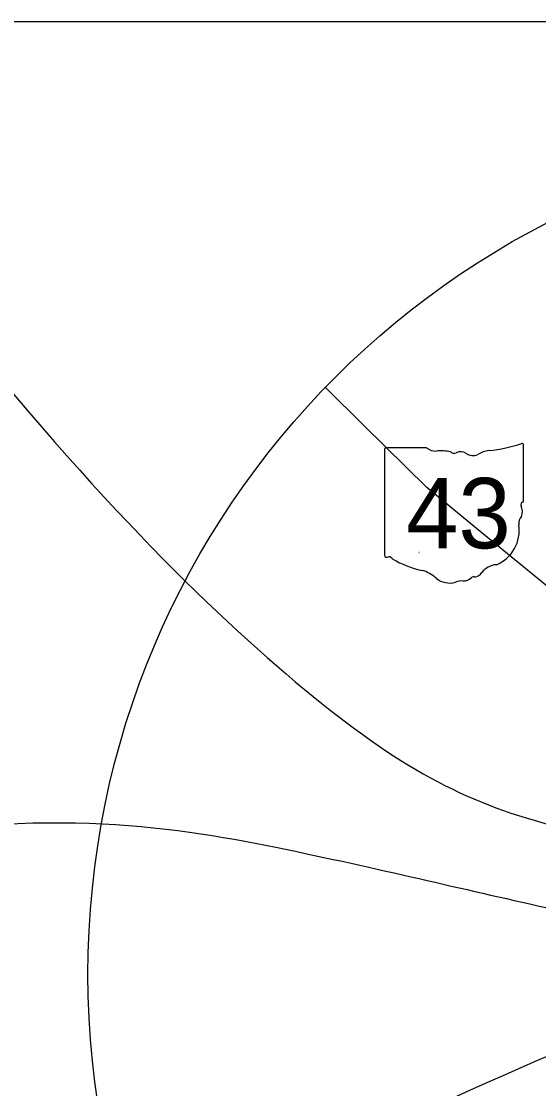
# Model space of a CAD drawing. Extents: x -202 to 1556, y 0 to 676.
# Drawn here: x 95.6 to 150.7, y 106.3 to 220 of the extents above; entities that cross this region are included whole.
import ezdxf

# ---------------------------------------------------------------- set-up
doc = ezdxf.new("R2010")
doc.units = 0
for name, color, linetype in [('Default', 7, 'Continuous'), ('GM_X_City_Street', 7, 'Continuous'), ('GM_X_Major_River_Text', 7, 'Continuous'), ('GM_X_Minor_River_Text', 7, 'Continuous'), ('SH_Data', 7, 'Continuous')]:
    doc.layers.add(name, color=color, linetype=linetype)

msp = doc.modelspace()

# ---------------------------------------------------------------- linework, layer by layer
at = {"layer": 'Default'}
msp.add_lwpolyline([(187.32, 118.77), (186.06, 119.26), (184.38, 120.64), (182.61, 122.34), (181.15, 124.21), (179.3, 126.09), (177.33, 128.46), (176.33, 129.83), (175.47, 131.38), (174.48, 133.74), (173.13, 138.32), (172.07, 141.13), (171.14, 142.74), (169.81, 144.47), (163.58, 149.95), (162.3, 151.06), (144.08, 165.95), (138.78, 170.32), (132.09, 176.89), (127.97, 181)], dxfattribs=at)
at = {"layer": 'GM_X_City_Street'}
for p, q in [((134.26, 174.37), (134.26, 163.12)), ((138.75, 174.57), (134.4, 174.57)), ((149.09, 168.96), (149.09, 174.85)), ((149.09, 168.96), (149.09, 168.96))]:
    msp.add_line(p, q, dxfattribs=at)
for centre, radius, start, end in [((134.43, 174.4), 0.172, 98.1301, 188.1301), ((139.78, 175.87), 1.67, 231.6195, 271.1119), ((140.33, 168.25), 5.98, 80.4867, 94.9883), ((141.69, 174.45), 0.481, 219.7921, 297.1024), ((142.4, 173.15), 1, 54.4667, 119.1411), ((145.81, 171.13), 3.16, 97.3462, 120.7689), ((143.81, 189.91), 15.73, 275.8445, 288.9065), ((148.92, 174.87), 0.165, 351.8621, 97.738), ((143.69, 174.94), 1.2, 233.8562, 294.8282), ((149.05, 168.52), 0.256, 107.944, 210.337), ((147.42, 167.78), 1.53, 340.033, 23.6496), ((148.91, 168.93), 0.177, 289.6038, 7.7341), ((149.68, 166.49), 1.12, 136.8065, 186.9296), ((144.69, 165.74), 3.93, 292.3089, 8.9858), ((134.43, 163.09), 0.173, 171.9584, 258.3066), ((134.46, 164.24), 1.32, 267.339, 280.6039), ((134.73, 162.47), 0.477, 29.7484, 93.2717), ((140.75, 172.58), 11.36, 240.4129, 257.1985), ((137.36, 158.06), 3.55, 47.1842, 75.836), ((146.35, 159.96), 2.15, 94.4031, 142.5768), ((141.21, 162.41), 2.26, 230.7004, 286.2918), ((142.51, 158.52), 1.85, 85.6951, 111.2099), ((142.67, 161.57), 1.2, 268.777, 315.5493), ((143.76, 160.48), 0.338, 65.7517, 132.6484), ((143.62, 162.02), 1.27, 282.8732, 323.2771)]:
    msp.add_arc(centre, radius, start, end, dxfattribs=at)
at = {"layer": 'GM_X_Major_River_Text'}
for p, q in [((143.31, 164.95), (143.31, 164.94)), ((143.31, 164.94), (143.31, 164.95)), ((143.31, 164.95), (143.31, 164.95)), ((143.32, 164.95), (143.32, 164.95)), ((143.32, 164.94), (143.32, 164.94)), ((137.95, 163.41), (137.94, 163.39)), ((137.97, 163.4), (137.96, 163.4)), ((137.96, 163.4), (137.97, 163.4)), ((137.96, 163.39), (137.96, 163.39)), ((137.97, 163.4), (137.97, 163.4)), ((137.97, 163.39), (137.97, 163.39))]:
    msp.add_line(p, q, dxfattribs=at)
msp.add_lwpolyline([(137.95, 163.41), (137.95, 163.39), (137.94, 163.39), (137.95, 163.41)], close=True, dxfattribs=at)
for points in [[(137.94, 163.39), (137.95, 163.39), (137.95, 163.39)], [(137.96, 163.39), (137.95, 163.39), (137.95, 163.41)], [(137.95, 163.39), (137.95, 163.39), (137.96, 163.39)]]:
    msp.add_lwpolyline(points, dxfattribs=at)
for points in [[(143.31, 164.94), (143.31, 164.94), (143.31, 164.95)], [(143.31, 164.95), (143.31, 164.95), (143.31, 164.95)], [(143.31, 164.95), (143.31, 164.95), (143.31, 164.95)], [(143.31, 164.95), (143.31, 164.95), (143.31, 164.95)], [(143.31, 164.95), (143.31, 164.95), (143.31, 164.95)], [(143.31, 164.95), (143.31, 164.95), (143.31, 164.95)], [(143.31, 164.95), (143.31, 164.95), (143.31, 164.95)], [(143.31, 164.95), (143.31, 164.95), (143.32, 164.95)], [(143.32, 164.95), (143.32, 164.95), (143.31, 164.95)], [(143.31, 164.95), (143.31, 164.95), (143.31, 164.95)], [(143.31, 164.95), (143.31, 164.95), (143.31, 164.95)], [(143.31, 164.95), (143.31, 164.95), (143.31, 164.95)], [(143.31, 164.95), (143.31, 164.95), (143.31, 164.95)], [(143.31, 164.95), (143.31, 164.95), (143.31, 164.95)], [(143.31, 164.95), (143.31, 164.95), (143.31, 164.95)], [(143.31, 164.95), (143.31, 164.95), (143.31, 164.95)], [(143.31, 164.95), (143.31, 164.95), (143.32, 164.94)], [(143.32, 164.95), (143.32, 164.95), (143.31, 164.95)], [(143.31, 164.95), (143.31, 164.95), (143.31, 164.95)], [(143.31, 164.95), (143.31, 164.95), (143.31, 164.95)], [(143.31, 164.95), (143.31, 164.95), (143.31, 164.95)], [(143.31, 164.95), (143.31, 164.95), (143.31, 164.95)], [(143.31, 164.95), (143.31, 164.95), (143.31, 164.95)], [(143.31, 164.95), (143.31, 164.95), (143.31, 164.95)], [(143.31, 164.95), (143.31, 164.95), (143.31, 164.95)], [(143.31, 164.95), (143.31, 164.95), (143.31, 164.95)], [(143.31, 164.95), (143.31, 164.95), (143.31, 164.95)], [(143.31, 164.95), (143.31, 164.95), (143.31, 164.95)], [(143.31, 164.95), (143.31, 164.95), (143.31, 164.95)], [(143.31, 164.95), (143.31, 164.95), (143.31, 164.95)], [(143.31, 164.95), (143.31, 164.95), (143.31, 164.95)], [(143.31, 164.95), (143.31, 164.95), (143.31, 164.95)], [(143.31, 164.95), (143.31, 164.95), (143.31, 164.95)], [(143.31, 164.95), (143.31, 164.95), (143.32, 164.95)], [(143.32, 164.94), (143.31, 164.94), (143.31, 164.94)], [(143.31, 164.94), (143.31, 164.94), (143.31, 164.94)], [(143.31, 164.94), (143.31, 164.94), (143.31, 164.94)], [(143.31, 164.94), (143.31, 164.94), (143.31, 164.94)], [(143.31, 164.94), (143.31, 164.94), (143.31, 164.94)], [(143.31, 164.94), (143.31, 164.94), (143.31, 164.94)], [(143.31, 164.94), (143.31, 164.94), (143.31, 164.94)], [(143.31, 164.94), (143.31, 164.94), (143.31, 164.94)], [(143.31, 164.94), (143.31, 164.94), (143.31, 164.94)], [(143.31, 164.94), (143.31, 164.94), (143.31, 164.94)], [(143.31, 164.94), (143.31, 164.94), (143.31, 164.94)], [(143.31, 164.94), (143.31, 164.94), (143.31, 164.94)], [(143.31, 164.94), (143.31, 164.94), (143.31, 164.94)], [(143.31, 164.94), (143.31, 164.94), (143.31, 164.94)], [(143.31, 164.94), (143.31, 164.94), (143.31, 164.94)], [(143.31, 164.94), (143.31, 164.94), (143.31, 164.94)], [(143.31, 164.94), (143.32, 164.94), (143.32, 164.94)], [(143.32, 164.94), (143.32, 164.94), (143.31, 164.94)], [(143.31, 164.94), (143.31, 164.94), (143.31, 164.94)], [(143.31, 164.94), (143.31, 164.94), (143.31, 164.94)], [(143.31, 164.94), (143.31, 164.94), (143.31, 164.94)], [(143.31, 164.94), (143.31, 164.94), (143.31, 164.94)], [(143.31, 164.94), (143.31, 164.94), (143.31, 164.94)], [(143.31, 164.94), (143.31, 164.94), (143.31, 164.94)], [(143.31, 164.94), (143.31, 164.94), (143.31, 164.94)], [(143.31, 164.94), (143.31, 164.94), (143.31, 164.94)], [(143.31, 164.94), (143.31, 164.94), (143.31, 164.94)], [(143.31, 164.94), (143.31, 164.94), (143.31, 164.94)], [(143.32, 164.95), (143.32, 164.95), (143.32, 164.95)], [(143.32, 164.95), (143.32, 164.95), (143.32, 164.95)], [(143.32, 164.95), (143.32, 164.95), (143.32, 164.95)], [(143.32, 164.95), (143.32, 164.95), (143.32, 164.95)], [(143.32, 164.95), (143.32, 164.95), (143.32, 164.95)], [(143.32, 164.95), (143.32, 164.95), (143.32, 164.95)], [(143.32, 164.95), (143.32, 164.95), (143.32, 164.95)], [(143.32, 164.95), (143.32, 164.95), (143.32, 164.95)], [(143.32, 164.95), (143.32, 164.95), (143.32, 164.95)], [(143.32, 164.95), (143.32, 164.95), (143.32, 164.95)], [(143.32, 164.95), (143.32, 164.95), (143.32, 164.95)], [(143.32, 164.95), (143.32, 164.95), (143.32, 164.95)], [(143.32, 164.95), (143.32, 164.95), (143.32, 164.95)], [(143.32, 164.95), (143.32, 164.95), (143.32, 164.95)], [(143.32, 164.95), (143.32, 164.95), (143.32, 164.95)], [(143.32, 164.95), (143.32, 164.95), (143.32, 164.95)], [(143.32, 164.95), (143.32, 164.95), (143.32, 164.95)], [(143.32, 164.95), (143.32, 164.95), (143.32, 164.95)], [(143.32, 164.95), (143.32, 164.95), (143.32, 164.95)], [(143.32, 164.95), (143.32, 164.95), (143.32, 164.95)], [(143.32, 164.95), (143.32, 164.95), (143.32, 164.95)], [(143.32, 164.95), (143.32, 164.95), (143.32, 164.95)], [(143.32, 164.95), (143.32, 164.95), (143.32, 164.95)], [(143.32, 164.95), (143.32, 164.95), (143.32, 164.95)], [(143.32, 164.95), (143.32, 164.95), (143.32, 164.95)], [(143.32, 164.95), (143.32, 164.95), (143.32, 164.95)], [(143.32, 164.95), (143.32, 164.95), (143.32, 164.95)], [(143.32, 164.95), (143.32, 164.95), (143.32, 164.95)], [(143.32, 164.95), (143.32, 164.95), (143.32, 164.95)], [(143.32, 164.94), (143.32, 164.94), (143.32, 164.94)], [(143.32, 164.94), (143.32, 164.94), (143.32, 164.94)], [(143.32, 164.94), (143.32, 164.94), (143.32, 164.94)], [(143.32, 164.94), (143.32, 164.94), (143.32, 164.94)], [(143.32, 164.94), (143.32, 164.94), (143.32, 164.94)], [(143.32, 164.94), (143.32, 164.94), (143.32, 164.94)], [(143.32, 164.94), (143.32, 164.94), (143.32, 164.94)], [(143.32, 164.94), (143.32, 164.94), (143.32, 164.94)], [(143.32, 164.94), (143.32, 164.94), (143.32, 164.94)], [(143.32, 164.94), (143.32, 164.94), (143.32, 164.94)], [(143.32, 164.94), (143.32, 164.94), (143.32, 164.94)], [(137.94, 163.39), (137.94, 163.39), (137.94, 163.39)], [(137.94, 163.39), (137.94, 163.39), (137.94, 163.39)], [(137.94, 163.39), (137.94, 163.39), (137.94, 163.39)], [(137.94, 163.39), (137.94, 163.39), (137.94, 163.39)], [(137.94, 163.39), (137.94, 163.39), (137.94, 163.39)], [(137.94, 163.39), (137.94, 163.39), (137.94, 163.39)], [(137.94, 163.39), (137.94, 163.39), (137.94, 163.39)], [(137.94, 163.39), (137.94, 163.39), (137.94, 163.39)], [(137.95, 163.41), (137.95, 163.41), (137.95, 163.41)], [(137.95, 163.41), (137.95, 163.41), (137.95, 163.41)], [(137.95, 163.41), (137.95, 163.41), (137.95, 163.41)], [(137.95, 163.41), (137.95, 163.41), (137.95, 163.41)], [(137.95, 163.41), (137.95, 163.41), (137.95, 163.41)], [(137.95, 163.41), (137.95, 163.41), (137.95, 163.41)], [(137.95, 163.41), (137.95, 163.41), (137.95, 163.41)], [(137.95, 163.41), (137.95, 163.41), (137.95, 163.41)], [(137.95, 163.39), (137.95, 163.39), (137.95, 163.39)], [(137.95, 163.39), (137.95, 163.39), (137.95, 163.39)], [(137.95, 163.39), (137.95, 163.39), (137.95, 163.39)], [(137.95, 163.39), (137.95, 163.39), (137.95, 163.39)], [(137.95, 163.39), (137.95, 163.39), (137.95, 163.39)], [(137.95, 163.39), (137.95, 163.39), (137.95, 163.39)], [(137.95, 163.39), (137.95, 163.39), (137.95, 163.39)], [(137.95, 163.39), (137.95, 163.39), (137.95, 163.39)], [(137.97, 163.41), (137.97, 163.41), (137.96, 163.41)], [(137.96, 163.41), (137.96, 163.41), (137.96, 163.4)], [(137.96, 163.4), (137.96, 163.4), (137.96, 163.4)], [(137.96, 163.4), (137.96, 163.41), (137.96, 163.41)], [(137.96, 163.41), (137.96, 163.41), (137.96, 163.41)], [(137.96, 163.41), (137.96, 163.41), (137.96, 163.41)], [(137.96, 163.41), (137.96, 163.41), (137.96, 163.41)], [(137.96, 163.41), (137.96, 163.41), (137.96, 163.41)], [(137.96, 163.41), (137.96, 163.41), (137.96, 163.41)], [(137.96, 163.41), (137.96, 163.41), (137.96, 163.41)], [(137.96, 163.41), (137.97, 163.41), (137.97, 163.41)], [(137.96, 163.4), (137.96, 163.4), (137.96, 163.4)], [(137.96, 163.4), (137.96, 163.4), (137.96, 163.4)], [(137.96, 163.4), (137.96, 163.4), (137.96, 163.4)], [(137.96, 163.4), (137.96, 163.4), (137.96, 163.4)], [(137.96, 163.4), (137.96, 163.4), (137.96, 163.4)], [(137.96, 163.4), (137.96, 163.4), (137.96, 163.4)], [(137.96, 163.4), (137.96, 163.4), (137.96, 163.4)], [(137.96, 163.4), (137.96, 163.4), (137.96, 163.4)], [(137.96, 163.4), (137.96, 163.4), (137.96, 163.4)], [(137.96, 163.4), (137.96, 163.4), (137.96, 163.4)], [(137.96, 163.4), (137.96, 163.4), (137.96, 163.4)], [(137.96, 163.4), (137.96, 163.4), (137.96, 163.4)], [(137.96, 163.4), (137.96, 163.4), (137.96, 163.4)], [(137.96, 163.39), (137.96, 163.39), (137.96, 163.39)], [(137.96, 163.39), (137.96, 163.39), (137.96, 163.39)], [(137.96, 163.39), (137.96, 163.39), (137.96, 163.39)], [(137.96, 163.39), (137.96, 163.39), (137.96, 163.39)], [(137.97, 163.39), (137.97, 163.39), (137.96, 163.39)], [(137.96, 163.39), (137.96, 163.39), (137.96, 163.39)], [(137.96, 163.39), (137.96, 163.39), (137.96, 163.39)], [(137.96, 163.39), (137.96, 163.39), (137.96, 163.39)], [(137.96, 163.39), (137.96, 163.39), (137.96, 163.39)], [(137.96, 163.39), (137.96, 163.39), (137.96, 163.39)], [(137.96, 163.39), (137.96, 163.39), (137.96, 163.39)], [(137.96, 163.39), (137.96, 163.39), (137.96, 163.39)], [(137.96, 163.39), (137.96, 163.39), (137.96, 163.39)], [(137.96, 163.39), (137.96, 163.39), (137.96, 163.39)], [(137.96, 163.39), (137.96, 163.39), (137.96, 163.39)], [(137.96, 163.39), (137.96, 163.39), (137.96, 163.39)], [(137.96, 163.39), (137.96, 163.39), (137.96, 163.39)], [(137.96, 163.39), (137.97, 163.39), (137.97, 163.39)], [(137.97, 163.4), (137.97, 163.41), (137.97, 163.41)], [(137.97, 163.41), (137.97, 163.41), (137.97, 163.41)], [(137.97, 163.41), (137.97, 163.41), (137.97, 163.41)], [(137.97, 163.41), (137.97, 163.41), (137.97, 163.41)], [(137.97, 163.41), (137.97, 163.41), (137.97, 163.4)], [(137.97, 163.39), (137.97, 163.39), (137.97, 163.4)], [(137.97, 163.4), (137.97, 163.4), (137.97, 163.4)], [(137.97, 163.4), (137.97, 163.4), (137.97, 163.4)], [(137.97, 163.4), (137.97, 163.4), (137.97, 163.4)], [(137.97, 163.4), (137.97, 163.4), (137.97, 163.4)], [(137.97, 163.4), (137.97, 163.4), (137.97, 163.4)], [(137.97, 163.4), (137.97, 163.4), (137.97, 163.4)], [(137.97, 163.4), (137.97, 163.4), (137.97, 163.4)], [(137.97, 163.4), (137.97, 163.4), (137.97, 163.4)], [(137.97, 163.4), (137.97, 163.4), (137.97, 163.4)], [(137.97, 163.4), (137.97, 163.4), (137.97, 163.4)], [(137.97, 163.4), (137.97, 163.4), (137.97, 163.4)], [(137.97, 163.4), (137.97, 163.4), (137.97, 163.4)], [(137.97, 163.4), (137.97, 163.4), (137.97, 163.4)], [(137.97, 163.4), (137.97, 163.4), (137.97, 163.4)], [(137.97, 163.4), (137.97, 163.4), (137.97, 163.4)], [(137.97, 163.4), (137.97, 163.4), (137.97, 163.39)], [(137.97, 163.39), (137.97, 163.39), (137.97, 163.39)], [(137.97, 163.39), (137.97, 163.39), (137.97, 163.39)], [(137.97, 163.39), (137.97, 163.39), (137.97, 163.39)], [(137.97, 163.39), (137.97, 163.39), (137.97, 163.39)], [(137.97, 163.39), (137.97, 163.39), (137.97, 163.39)], [(137.97, 163.39), (137.97, 163.39), (137.97, 163.39)], [(137.97, 163.39), (137.97, 163.39), (137.97, 163.39)], [(137.97, 163.39), (137.97, 163.39), (137.97, 163.39)], [(137.97, 163.39), (137.97, 163.39), (137.97, 163.39)], [(137.97, 163.39), (137.97, 163.39), (137.97, 163.39)]]:
    msp.add_open_spline(points, degree=2, dxfattribs=at)
at = {"layer": 'GM_X_Minor_River_Text'}
msp.add_line((30, 220), (640, 220), dxfattribs=at)
at = {"layer": 'SH_Data'}
msp.add_circle((192.68, 118.45), 90, dxfattribs=at)
for points in [[(86.29, 190.69), (102.24, 170.36), (128.97, 144.07), (149.56, 133.27), (172.62, 130.54), (191.35, 132)], [(79.52, 132.82), (99.83, 136.42), (127.65, 131.33), (152.16, 125.11), (172.51, 121.38), (186.79, 122.16)], [(72.68, 92.44), (98.67, 92.22), (111.17, 94.55), (131, 99.43), (168.35, 118.15), (182.67, 118.56)]]:
    msp.add_open_spline(points, degree=3, dxfattribs=at)

# ---------------------------------------------------------------- texts
at = {"layer": 'GM_X_City_Street'}
msp.add_text('43', height=7.5, dxfattribs=at).set_placement((136.56, 163.85))

doc.saveas('drawing.dxf')
